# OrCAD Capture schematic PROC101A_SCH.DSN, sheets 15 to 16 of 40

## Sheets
15 38. SoC POWER SUPPLY: size C; title: SoC POWER SUPPLY
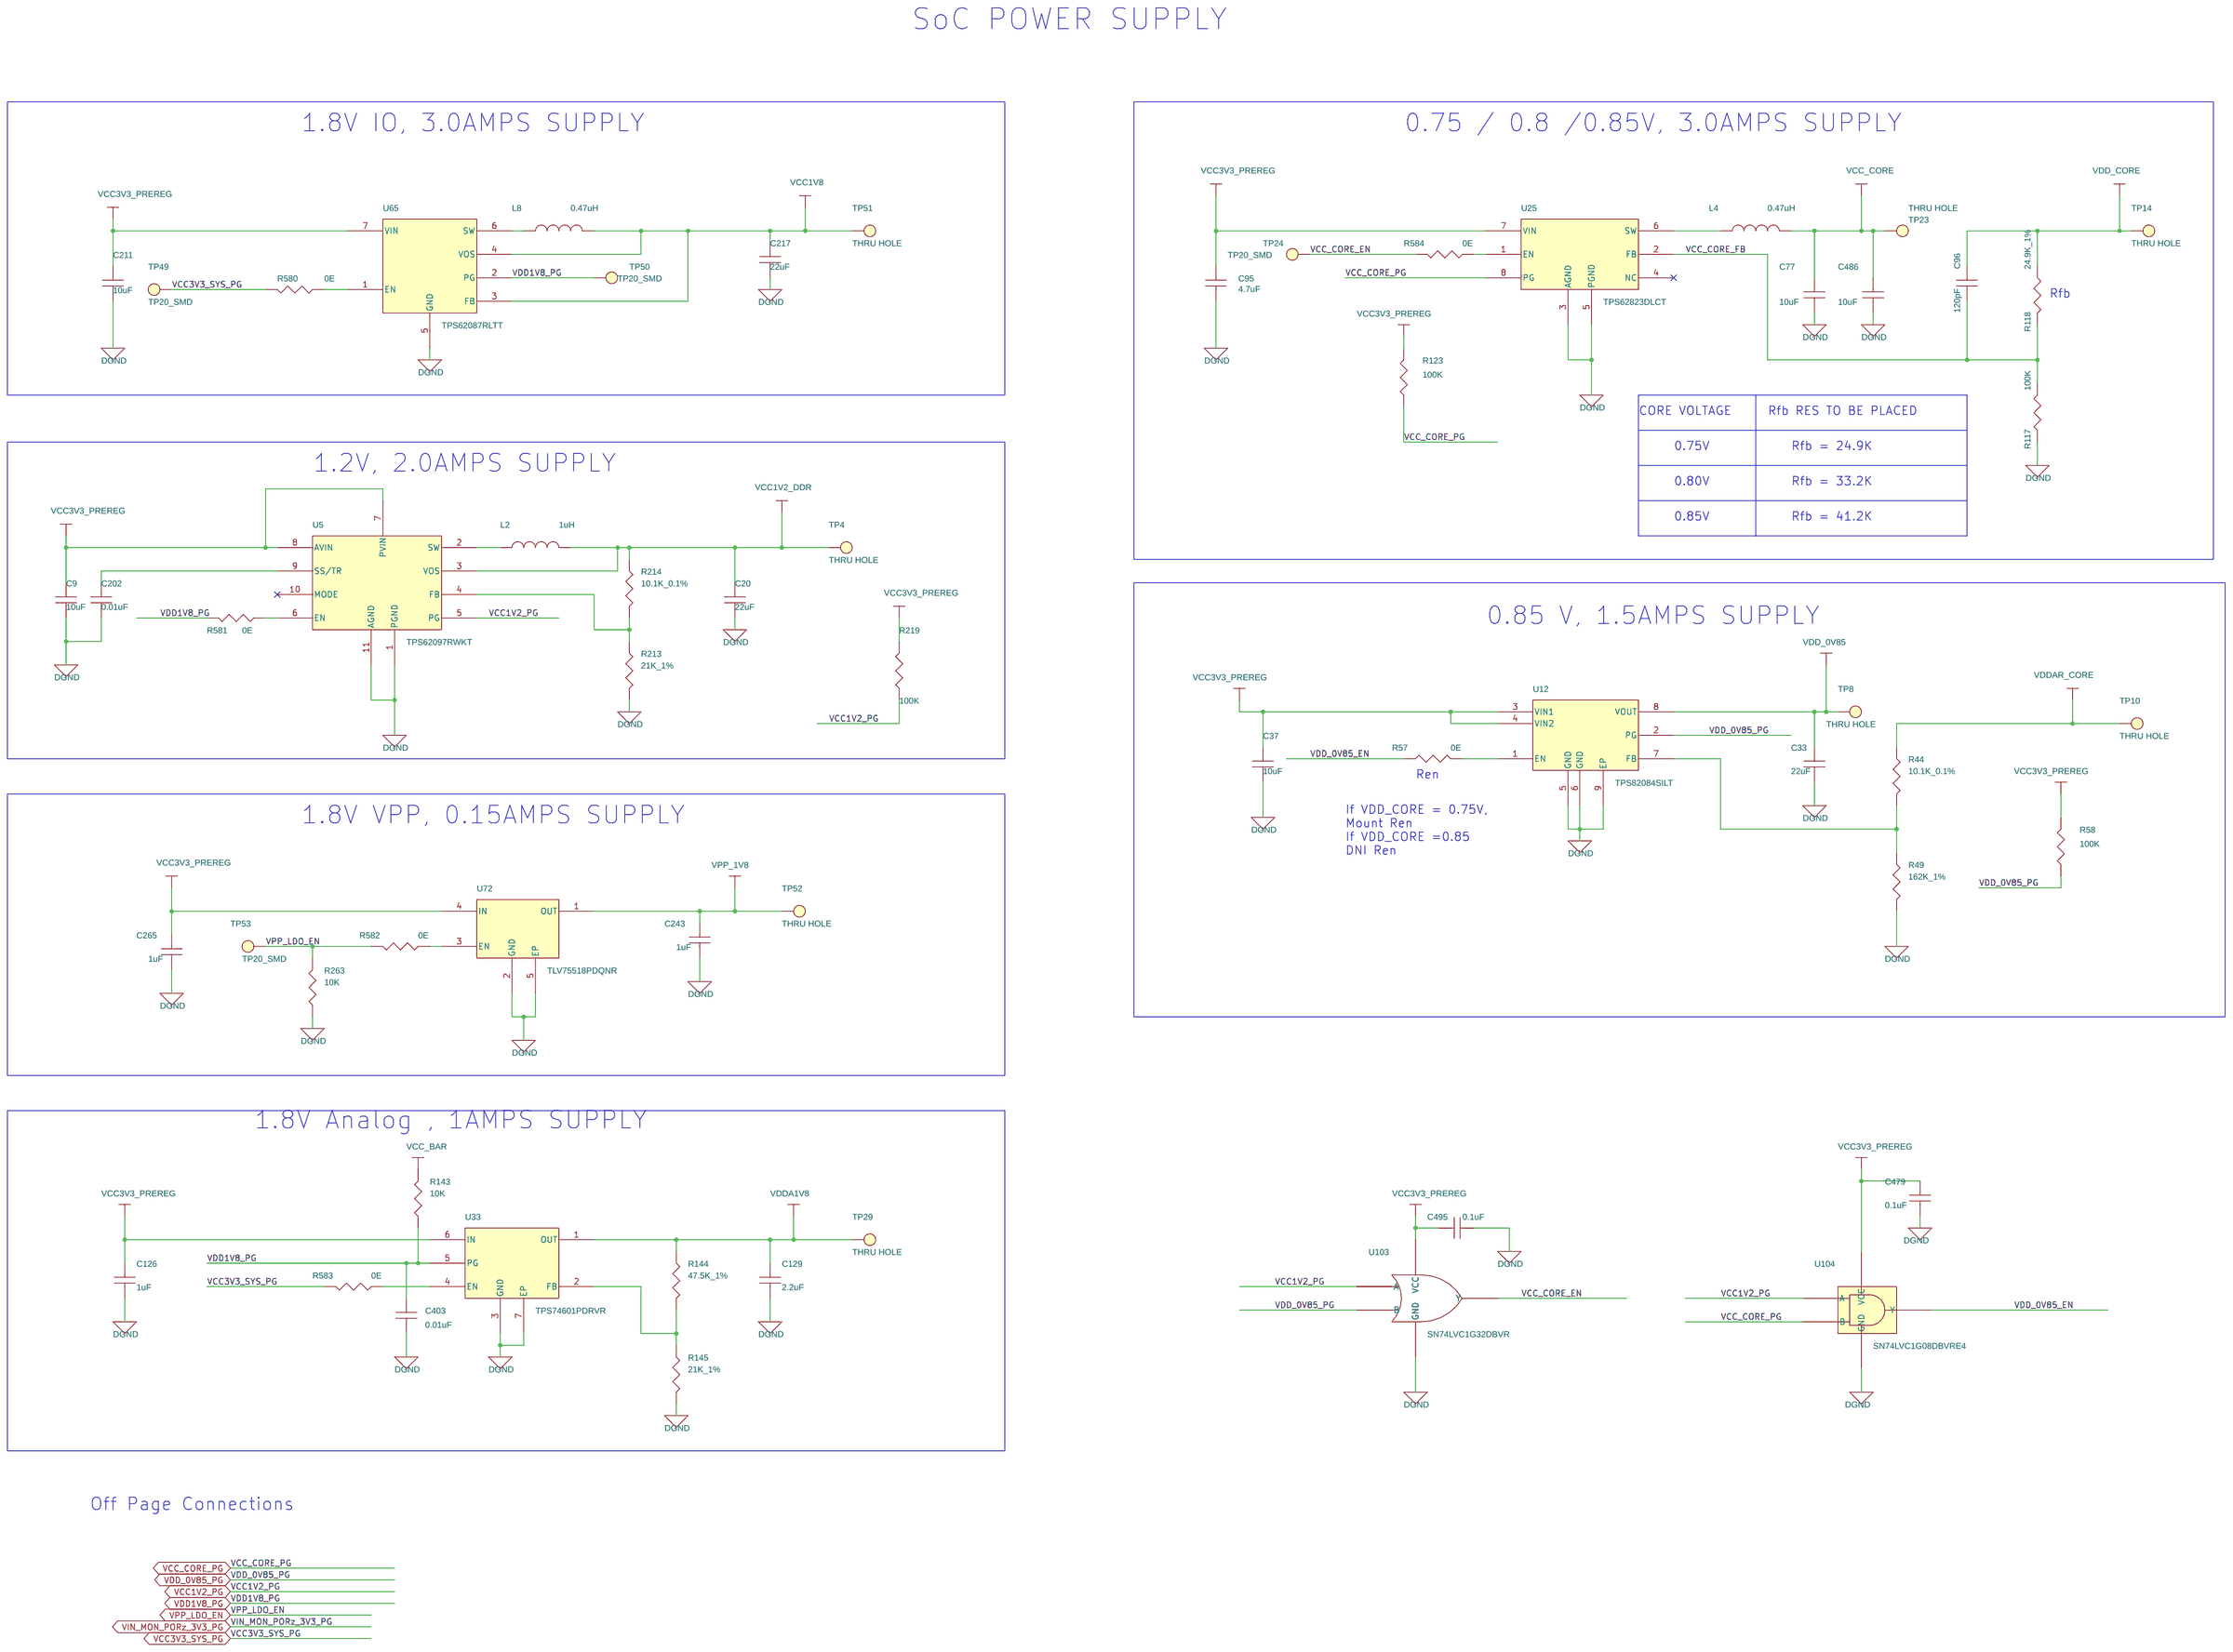
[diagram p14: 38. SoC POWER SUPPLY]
16 39.PERIPHERAL POWER SUPPLY: size C; title: PERIPHERAL POWER SUPPLY
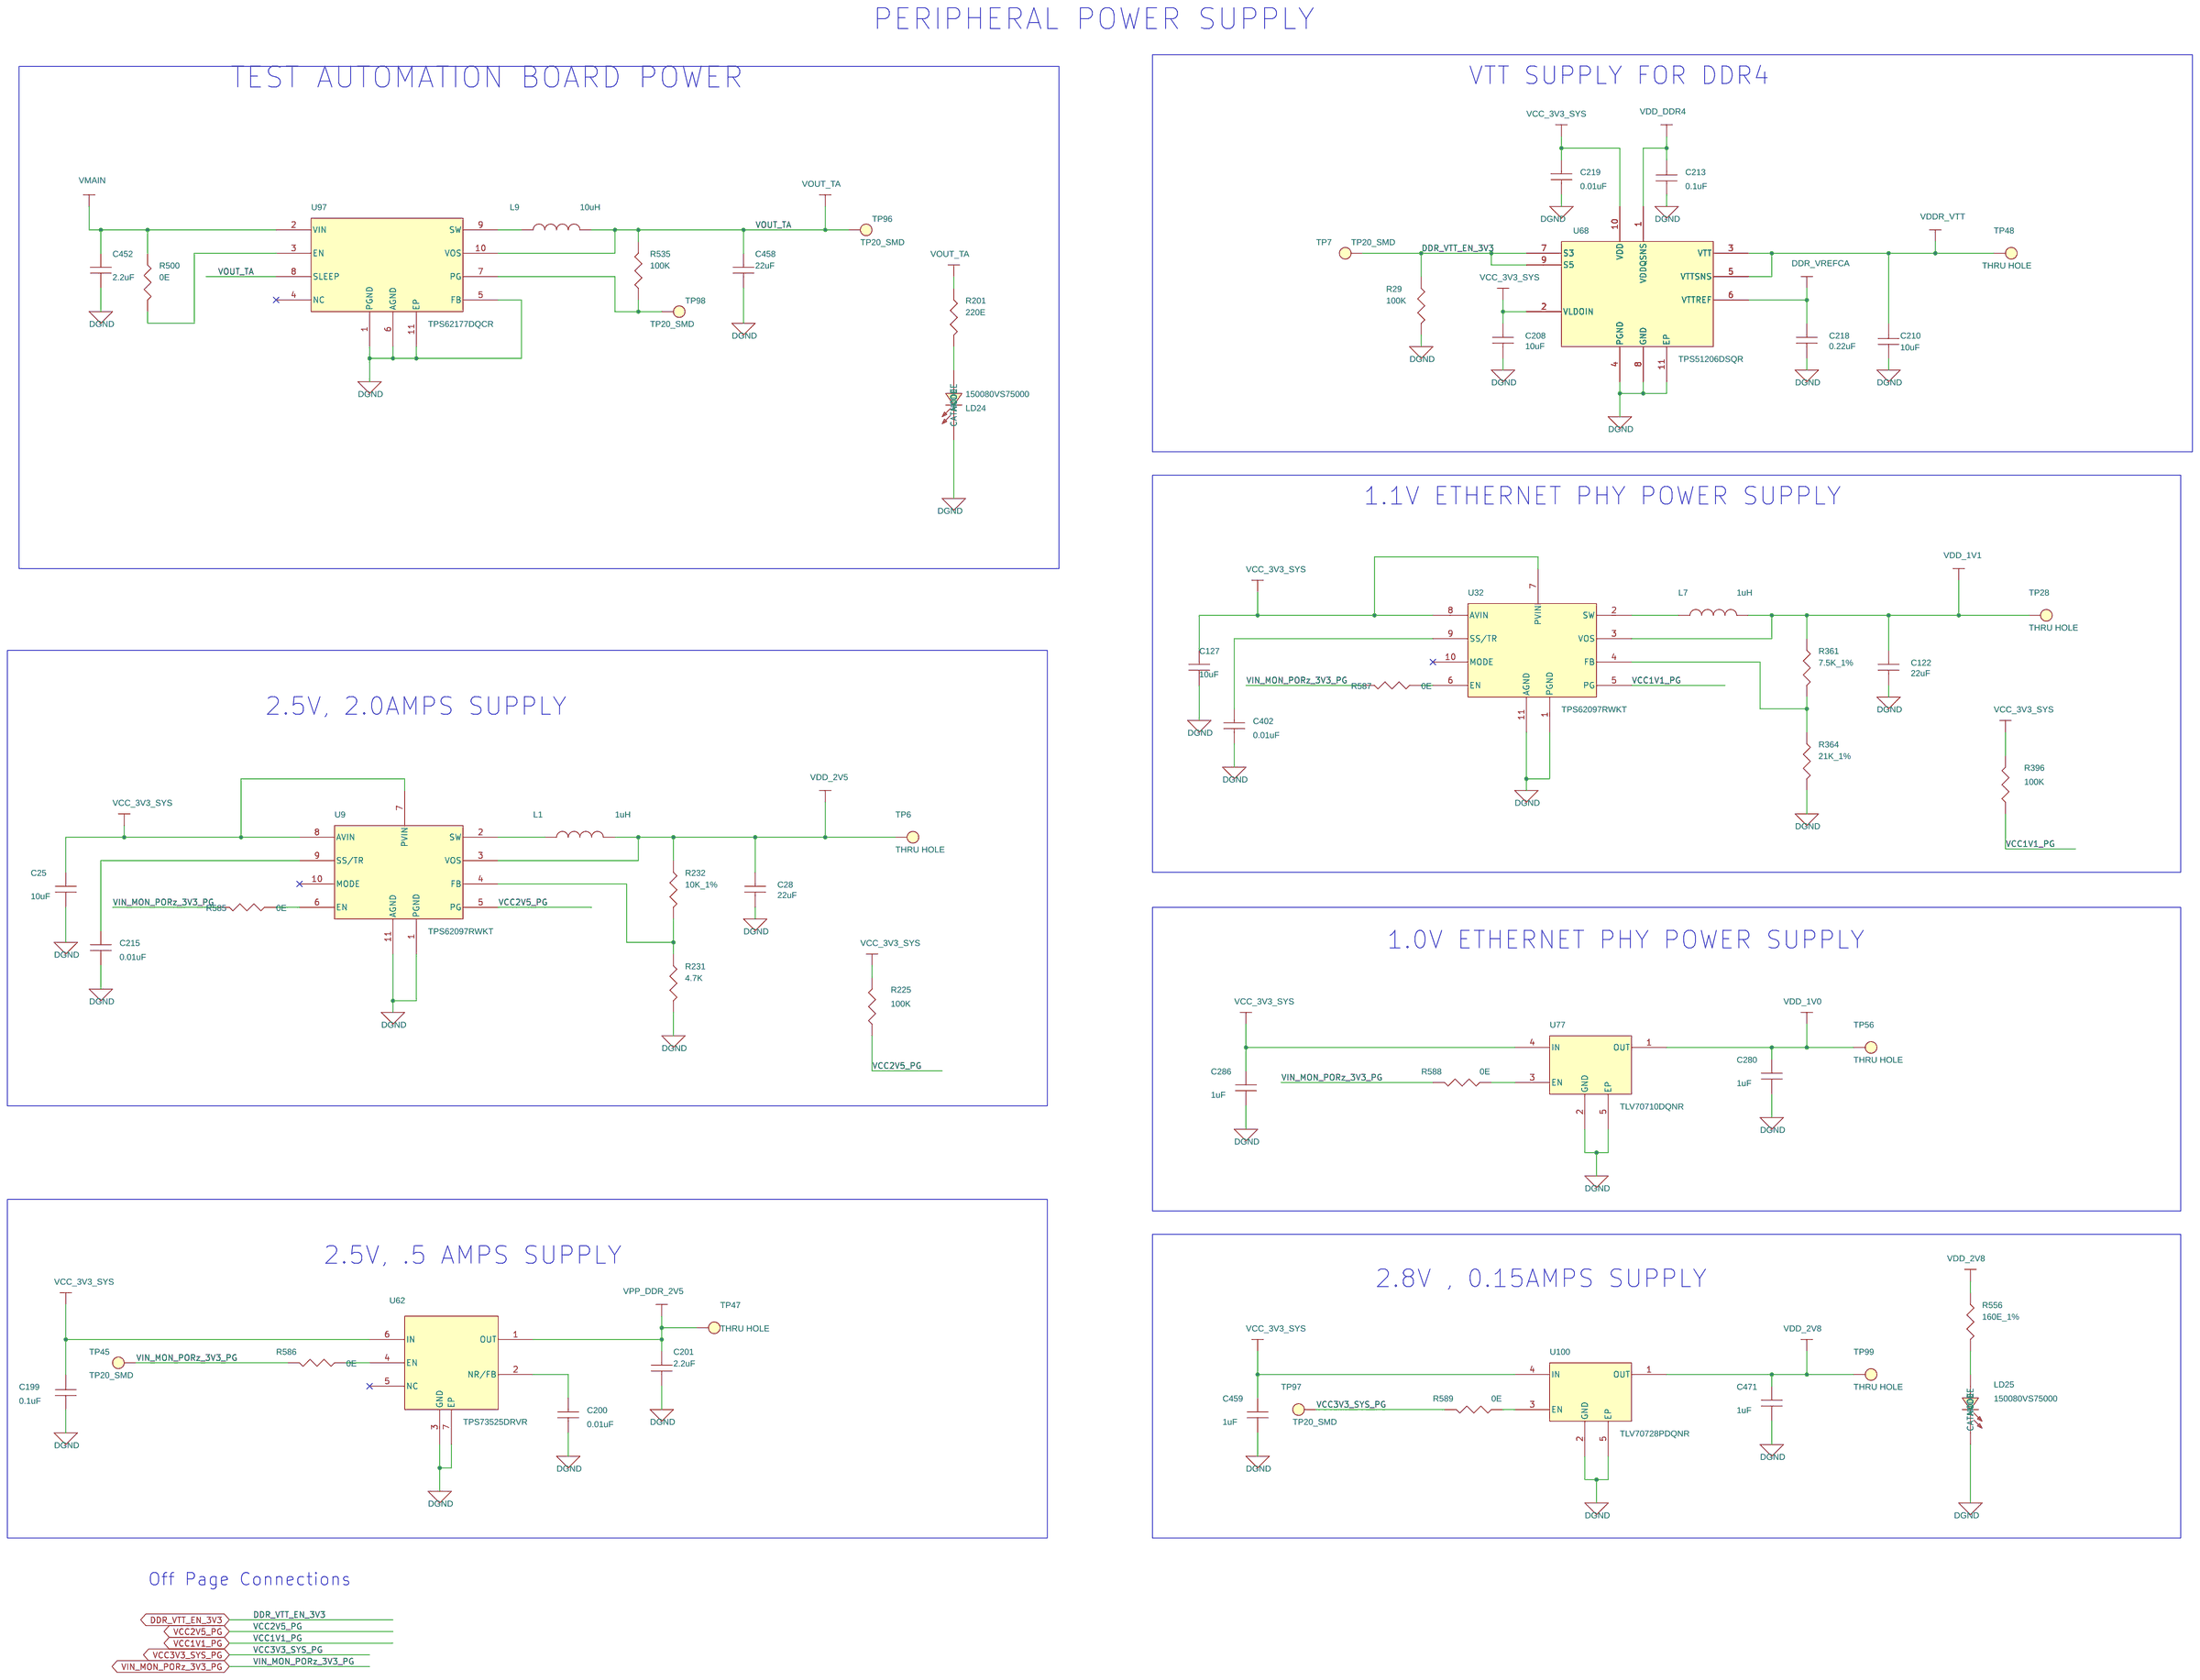
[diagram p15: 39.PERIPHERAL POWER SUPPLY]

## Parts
sheet 38. SoC POWER SUPPLY
C9  10uF  [CAP0402_0-75]
C20  22uF  [CAP0603_1]
C33  22uF  [CAP0603_1]
C37  10uF  [CAP0402_0-75]
C77  10uF  [CAP0402_0-75]
C95  4.7uF  [CAP0603_1]
C96  120pF  [CAP0402_0-75]
C126  1uF  [CAP0402_0-75]
C129  2.2uF  [CAP0402_0-75]
C202  0.01uF  [CAP0402_0-75]
C211  10uF  [CAP0603_1]
C217  22uF  [CAP0603_1]
C243  1uF  [CAP0402_0-75]
C265  1uF  [CAP0402_0-75]
C403  0.01uF  [CAP0402_0-75]
C479  0.1uF  [CAP0402_0-75]
C486  10uF  [CAP0402_0-75]
C495  0.1uF  [CAP0402_0-75]
L2  1uH  [IND_744316100_230X220_SMD_4-3]
L4  0.47uH  [IND_744373460047_270X270_SMD_3]
L8  0.47uH  [IND_744373460047_270X270_SMD_3]
R44  10.1K_0.1%  [RES0603_0-75]
R49  162K_1%  [RES0402_0-5]
R57  0E  [RES0402_0-5]
R58  100K  [RES0402_0-5]
R117  100K  [RES0402_0-5]
R118  24.9K_1%  [RES0402_0-5]
R123  100K  [RES0402_0-5]
R143  10K  [RES0402_0-5]
R144  47.5K_1%  [RES0402_0-5]
R145  21K_1%  [RES0402_0-5]
R213  21K_1%  [RES0402_0-5]
R214  10.1K_0.1%  [RES0603_0-75]
R219  100K  [RES0402_0-5]
R263  10K  [RES0402_0-5]
R580  0E  [RES0402_0-5]
R581  0E  [RES0402_0-5]
R582  0E  [RES0402_0-5]
R583  0E  [RES0402_0-5]
R584  0E  [RES0402_0-5]
TP4  THRU HOLE  [TP_40X65]
TP8  THRU HOLE  [TP_40X65]
TP10  THRU HOLE  [TP_40X65]
TP14  THRU HOLE  [TP_40X65]
TP23  THRU HOLE  [TP_40X65]
TP24  TP20_SMD  [TP20_SMD]
TP29  THRU HOLE  [TP_40X65]
TP49  TP20_SMD  [TP20_SMD]
TP50  TP20_SMD  [TP20_SMD]
TP51  THRU HOLE  [TP_40X65]
TP52  THRU HOLE  [TP_40X65]
TP53  TP20_SMD  [TP20_SMD]
U5  TPS62097RWKT  [VQFNHR11_TPS62097_80X80_1]
U12  TPS82084SILT  [uSIP8_TPS82084_110X120_1-4]
U25  TPS62823DLCT  [VSONHR8_TPS62823_60X80_1]
U33  TPS74601PDRVR  [SON6_25-59_85X85_0-8]
U65  TPS62087RLTT  [VSONHR7_TPS62085_80X80_1]
U72  TLV75518PDQNR  [X2SON4_TLV71318P_40X40_0-4]
U103  SN74LVC1G32DBVR  [SOT23-5_1-5]
U104  SN74LVC1G08DBVRE4  [SOT23-5]
sheet 39.PERIPHERAL POWER SUPPLY
C25  10uF  [CAP0402_0-75]
C28  22uF  [CAP0603_1]
C122  22uF  [CAP0603_1]
C127  10uF  [CAP0402_0-75]
C199  0.1uF  [CAP0402_0-75]
C200  0.01uF  [CAP0402_0-75]
C201  2.2uF  [CAP0402_0-75]
C208  10uF  [CAP0402_0-75]
C210  10uF  [CAP0402_0-75]
C213  0.1uF  [CAP0402_0-75]
C215  0.01uF  [CAP0402_0-75]
C218  0.22uF  [CAP0201_0-5]
C219  0.01uF  [CAP0402_0-75]
C280  1uF  [CAP0402_0-75]
C286  1uF  [CAP0402_0-75]
C402  0.01uF  [CAP0402_0-75]
C452  2.2uF  [CAP0603_1]
C458  22uF  [CAP0805_1-5]
C459  1uF  [CAP0402_0-75]
C471  1uF  [CAP0402_0-75]
L1  1uH  [IND_744316100_230X220_SMD_4-3]
L7  1uH  [IND_744316100_230X220_SMD_4-3]
L9  10uH  [IND_74438336100_130X130_SMD_2]
LD24  150080VS75000  [LED_150080VS75000_80X50_SMD_0-8]
LD25  150080VS75000  [LED_150080VS75000_80X50_SMD_0-8]
R29  100K  [RES0402_0-5]
R201  220E  [RES0402_0-5]
R225  100K  [RES0402_0-5]
R231  4.7K  [RES0402_0-5]
R232  10K_1%  [RES0402_0-5]
R361  7.5K_1%  [RES0402_0-5]
R364  21K_1%  [RES0402_0-5]
R396  100K  [RES0402_0-5]
R500  0E  [RES0402_0-5]
R535  100K  [RES0402_0-5]
R556  160E_1%  [RES0402_0-5]
R585  0E  [RES0402_0-5]
R586  0E  [RES0402_0-5]
R587  0E  [RES0402_0-5]
R588  0E  [RES0402_0-5]
R589  0E  [RES0402_0-5]
TP6  THRU HOLE  [TP_40X65]
TP7  TP20_SMD  [TP20_SMD]
TP28  THRU HOLE  [TP_40X65]
TP45  TP20_SMD  [TP20_SMD]
TP47  THRU HOLE  [TP_40X65]
TP48  THRU HOLE  [TP_40X65]
TP56  THRU HOLE  [TP_40X65]
TP96  TP20_SMD  [TP20_SMD]
TP97  TP20_SMD  [TP20_SMD]
TP98  TP20_SMD  [TP20_SMD]
TP99  THRU HOLE  [TP_40X65]
U9  TPS62097RWKT  [VQFNHR11_TPS62097_80X80_1]
U32  TPS62097RWKT  [VQFNHR11_TPS62097_80X80_1]
U62  TPS73525DRVR  [SON6_25-59_85X85_0-8]
U68  TPS51206DSQR  [EDFN10_15-74_80X80_0-8]
U77  TLV70710DQNR  [X2SON4_TLV71318P_40X40_0-4]
U97  TPS62177DQCR  [WSON10_19-68_80X120_0-8]
U100  TLV70728PDQNR  [X2SON4_TLV71318P_40X40_0-4]

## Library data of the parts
C9 C25 C37 C77 C127 C208 C210 C486 = CAP: CAP CERAMIC 10uF 10V 20% X5R 0402; Chkd/date: MANIRAJA/300520; Crtd /date: ALVY/260520; Custom_Duty: 15%; Customs_HS_Code: 85322990; Distributor_name: DIGIKEY; Distributor_part_number: 490-GRM155R61A106ME11DTR-ND; Footprint Path: Y:\MIS_DATABASE\Library\ALTIUM_TOOL\PCB_FOOTPRINTS\Altium_Footprint_Lib.PcbLib; Height: 0.55MM; Library Path: Y:\MIS_DATABASE\Library\ALTIUM_TOOL\SCHEMATICS_PARTS\MS_DISCRETE_Library.schlib; Mfr_name: MURATA; Mfr_part_number: GRM155R61A106ME11D; Mistral Part No: 120013110019-R; Package: 0402; Part_type: CAPACITORS\CERAMIC; Project: QCS610_NANOSOM; RoHS: RoHS; Temperature: -55°C+85°C; Tolerance: 20%; Voltage: 10V; Wattage: NA; Weight: 3.1mg; Datasheet: Y:\MIS_DATABASE\DATASHEETS\CAPACITORS\MURATA-GXX-SER_NOV17.PDF
C20 C28 C33 C122 C217 = CAP: CAP CERAMIC 22uF 6.3V 20% X5R 0603; Chkd/date: JEBRAN/090915; Crtd /date: JEBRAN/090915; Custom_Duty: 15%; Customs_HS_Code: 85322990; Distributor_name: DIGIKEY; Distributor_part_number: 490-7611-2-ND; Footprint Path: Y:\MIS_DATABASE\Library\ALTIUM_TOOL\PCB_FOOTPRINTS\Altium_Footprint_Lib.PcbLib; Height: 1.00MM; Library Path: Y:\MIS_DATABASE\Library\ALTIUM_TOOL\SCHEMATICS_PARTS\MS_DISCRETE_Library.schlib; Mfr_name: MURATA; Mfr_part_number: GRM188R60J226MEA0; Mistral Part No: 120015090007-R; Package: 0603; Part_type: CAPACITORS\CERAMIC; Project: OCTBTS_3000; RoHS: RoHS; Temperature: -55°C+85°C; Tolerance: 20%; Voltage: 6.3V; Wattage: NA; Weight: 6.3mg; Datasheet: Y:\MIS_DATABASE\DATASHEETS\CAPACITORS\MURATA-GXX-SER_NOV17.PDF
C95 = CAP: CAP CERAMIC 4.7uF 16V 10% X5R 0603; Chkd/date: MANIRAJA/131217; Crtd /date: ALVY/131217; Custom_Duty: 15%; Customs_HS_Code: 85322990; Distributor_name: DIGIKEY; Distributor_part_number: 311-1785-1-ND; Footprint Path: Y:\MIS_DATABASE\Library\ALTIUM_TOOL\PCB_FOOTPRINTS\Altium_Footprint_Lib.PcbLib; Height: 0.95MM; Library Path: Y:\MIS_DATABASE\Library\ALTIUM_TOOL\SCHEMATICS_PARTS\MS_DISCRETE_Library.schlib; Mfr_name: YAGEO AMERICA; Mfr_part_number: CC0603KRX5R7BB475; Mistral Part No: 120011050004-R; Package: 0603; Part_type: CAPACITORS\CERAMIC; Project: ASL_LIU_TYPE-II; RoHS: RoHS; Temperature: -55°C+85°C; Tolerance: 10%; Voltage: 16V; Wattage: NA; Weight: 2mg; Datasheet: Y:\MIS_DATABASE\DATASHEETS\CAPACITORS\YACC-X5R.PDF
C96 = CAP: CAP CERAMIC 120pF 50V 5% C0G(NP0) 0402; Chkd/date: MANIRAJA/080520; Crtd /date: ALVY/070520; Custom_Duty: 15%; Customs_HS_Code: 85322990; Distributor_name: DIGIKEY; Distributor_part_number: 311-3337-1-ND; Footprint Path: Y:\MIS_DATABASE\Library\ALTIUM_TOOL\PCB_FOOTPRINTS\Altium_Footprint_Lib.PcbLib; Height: 0.55MM; Library Path: Y:\MIS_DATABASE\Library\ALTIUM_TOOL\SCHEMATICS_PARTS\MS_DISCRETE_Library.schlib; Mfr_name: YAGEO AMERICA; Mfr_part_number: CC0402JRNPO9BN121; Mistral Part No: 120014040005-R; Package: 0402; Part_type: CAPACITORS\CERAMIC; Project: AM64x-GP_EVM BRD; RoHS: RoHS; Temperature: -55°C+125°C; Tolerance: 5%; Voltage: 50V; Wattage: NA; Weight: 12mg; Datasheet: Y:\MIS_DATABASE\DATASHEETS\CAPACITORS\YACC-NPO.PDF
C126 C243 C265 C280 C286 C459 C471 = CAP: CAP CERAMIC 1uF 10V 20% X5R 0402; Chkd/date: MANIRAJA/210820; Crtd /date: ALVY/190820; Custom_Duty: 15%; Customs_HS_Code: 85322990; Distributor_name: DIGIKEY; Distributor_part_number: 732-7489-1-ND; Footprint Path: Y:\MIS_DATABASE\Library\ALTIUM_TOOL\PCB_FOOTPRINTS\Altium_Footprint_Lib.PcbLib; Height: 0.55MM; Library Path: Y:\MIS_DATABASE\Library\ALTIUM_TOOL\SCHEMATICS_PARTS\MS_DISCRETE_Library.schlib; Mfr_name: WURTH ELECTRONICS; Mfr_part_number: 885012105012; Mistral Part No: 120020080009-R; Package: 0402; Part_type: CAPACITORS\CERAMIC; Project: AM64x_EVM_BRD; RoHS: RoHS; Temperature: -55°C+85°C; Tolerance: 20%; Voltage: 10V; Wattage: NA; Weight: 0.65mg; Datasheet: Y:\MIS_DATABASE\DATASHEETS\CAPACITORS\885012105012.PDF
C129 C201 = CAP: CAP CERAMIC 2.2uF 10V 20% X5R 0402; Chkd/date: MANIRAJA/170820; Crtd /date: ALVY/170820; Custom_Duty: 15%; Customs_HS_Code: 85322990; Distributor_name: DIGIKEY; Distributor_part_number: 732-7490-1-ND; Footprint Path: Y:\MIS_DATABASE\Library\ALTIUM_TOOL\PCB_FOOTPRINTS\Altium_Footprint_Lib.PcbLib; Height: 0.55MM; Library Path: Y:\MIS_DATABASE\Library\ALTIUM_TOOL\SCHEMATICS_PARTS\MS_DISCRETE_Library.schlib; Mfr_name: WURTH ELECTRONICS; Mfr_part_number: 885012105013; Mistral Part No: 120019040036-R; Package: 0402; Part_type: CAPACITORS\CERAMIC; Project: AM64x_EVM_BRD; RoHS: RoHS; Temperature: -55°C+85°C; Tolerance: 20%; Voltage: 10V; Wattage: NA; Weight: 0.65mg; Datasheet: Y:\MIS_DATABASE\DATASHEETS\CAPACITORS\885012105013.PDF
C200 C202 C215 C219 C402 C403 = CAP: CAP CERAMIC 0.01uF 25V 10% X7R 0402; Chkd/date: MANIRAJA/170820; Crtd /date: ALVY/170820; Custom_Duty: 15%; Customs_HS_Code: 85322990; Distributor_name: DIGIKEY; Distributor_part_number: 732-7545-1-ND; Footprint Path: Y:\MIS_DATABASE\Library\ALTIUM_TOOL\PCB_FOOTPRINTS\Altium_Footprint_Lib.PcbLib; Height: 0.55MM; Library Path: Y:\MIS_DATABASE\Library\ALTIUM_TOOL\SCHEMATICS_PARTS\MS_DISCRETE_Library.schlib; Mfr_name: WURTH ELECTRONICS; Mfr_part_number: 885012205050; Mistral Part No: 120011090040-R; Package: 0402; Part_type: CAPACITORS\CERAMIC; Project: AM64x_EVM_BRD; RoHS: RoHS; Temperature: -55°C+125°C; Tolerance: 10%; Voltage: 25V; Wattage: NA; Weight: 0.65mg; Datasheet: Y:\MIS_DATABASE\DATASHEETS\CAPACITORS\885012205050.PDF
C211 = CAP: CAP CERAMIC 10uF 35V 20% X5R 0603; Chkd/date: MANIRAJA/170519; Crtd /date: ALVY/160519; Custom_Duty: 15%; Customs_HS_Code: 85322990; Distributor_name: DIGIKEY; Distributor_part_number: 490-13248-1-ND; Footprint Path: Y:\MIS_DATABASE\Library\ALTIUM_TOOL\PCB_FOOTPRINTS\Altium_Footprint_Lib.PcbLib; Height: 1.00MM; Library Path: Y:\MIS_DATABASE\Library\ALTIUM_TOOL\SCHEMATICS_PARTS\MS_DISCRETE_Library.schlib; Mfr_name: MURATA; Mfr_part_number: GRM188R6YA106MA73D; Mistral Part No: 120019050016-R; Package: 0603; Part_type: CAPACITORS\CERAMIC; Project: BRUKER_SD820_COMMONDO; RoHS: RoHS; Temperature: -55°C+85°C; Tolerance: 20%; Voltage: 35V; Wattage: NA; Weight: 9mg; Datasheet: Y:\MIS_DATABASE\DATASHEETS\CAPACITORS\GRM188R6YA106MA73.PDF
C199 C213 C479 C495 = CAP: CAP CERAMIC 0.1uF 25V 20% X5R 0402; Alt_Mfr_name: YAGEO AMERICA; Alt_Mfr_part_number: CC0402KRX5R8BB104; Chkd/date: MANIRAJA/170820; Crtd /date: ALVY/170820; Custom_Duty: 15%; Customs_HS_Code: 85322990; Distributor_name: DIGIKEY; Distributor_part_number: 732-7495-1-ND; Footprint Path: Y:\MIS_DATABASE\Library\ALTIUM_TOOL\PCB_FOOTPRINTS\Altium_Footprint_Lib.PcbLib; Height: 0.55MM; Library Path: Y:\MIS_DATABASE\Library\ALTIUM_TOOL\SCHEMATICS_PARTS\MS_DISCRETE_Library.schlib; Mfr_name: WURTH ELECTRONICS; Mfr_part_number: 885012105018; Mistral Part No: 120020080003-R; Package: 0402; Part_type: CAPACITORS\CERAMIC; Project: AM64x_EVM_BRD; RoHS: RoHS; Temperature: -55°C+85°C; Tolerance: 20%; Voltage: 25V; Wattage: NA; Weight: 0.65mg; Datasheet: Y:\MIS_DATABASE\DATASHEETS\CAPACITORS\885012105018.PDF
L1 L2 L7 = INDUCTOR: IND HI-CURRENT 1uH 11.5A 20% SMD; Chkd/date: MANIRAJA/280520; Crtd /date: ALVY/280520; Custom_Duty: 24%; Customs_HS_Code: 85437099; Distributor_name: DIGIKEY; Distributor_part_number: 732-6176-1-ND; Footprint Path: Y:\MIS_DATABASE\Library\ALTIUM_TOOL\PCB_FOOTPRINTS\Altium_Footprint_Lib.PcbLib; Height: 4.30MM; Library Path: Y:\MIS_DATABASE\Library\ALTIUM_TOOL\SCHEMATICS_PARTS\MS_DISCRETE_Library.schlib; Mfr_name: WURTH ELECTRONICS; Mfr_part_number: 744316100; Mistral Part No: 130020050041-R; Package: SMD; Project: AM64x-GP_EVM BRD; RoHS: RoHS; Temperature: -40°C+150°C; Tolerance: 20%; Voltage: NA; Wattage: NA; Weight: 570mg; Datasheet: Y:\MIS_DATABASE\DATASHEETS\DISCRETES\INDUCTORS\744316100.PDF
L4 L8 = INDUCTOR: IND POWER 0.47uH 11.5A 20% SMD; Chkd/date: MANIRAJA/130820; Crtd /date: ALVY/130820; Custom_Duty: 24%; Customs_HS_Code: 85437099; Distributor_name: DIGIKEY; Distributor_part_number: 732-3366-1-ND; Footprint Path: Y:\MIS_DATABASE\Library\ALTIUM_TOOL\PCB_FOOTPRINTS\Altium_Footprint_Lib.PcbLib; Height: 3.00MM; Library Path: Y:\MIS_DATABASE\Library\ALTIUM_TOOL\SCHEMATICS_PARTS\MS_DISCRETE_Library.schlib; Mfr_name: WURTH ELECTRONICS; Mfr_part_number: 744373460047; Mistral Part No: 130020080011-R; Package: SMD; Project: AM64x_EVM_BRD; RoHS: RoHS; Temperature: -40°C+125°C; Tolerance: 20%; Voltage: NA; Wattage: NA; Weight: 719mg; Datasheet: Y:\MIS_DATABASE\DATASHEETS\DISCRETES\INDUCTORS\744373460047.PDF
R44 R214 = RESISTOR: RES 10.1K 1/8W 0.1% AUTO 0603; Chkd/date: MANIRAJA/090420; Crtd /date: ALVY/080420; Custom_Duty: 15%; Customs_HS_Code: 85332119; Distributor_name: DIGIKEY; Distributor_part_number: 541-3907-1-ND; Footprint Path: Y:\MIS_DATABASE\Library\ALTIUM_TOOL\PCB_FOOTPRINTS\Altium_Footprint_Lib.PcbLib; Height: 0.55MM; Library Path: Y:\MIS_DATABASE\Library\ALTIUM_TOOL\SCHEMATICS_PARTS\MS_DISCRETE_Library.schlib; Mfr_name: VISHAY; Mfr_part_number: TNPW060310K1BEEA; Mistral Part No: 110020040008-R; Package: 0603; Part_type: RESISTORS\FIXED; Project: AM64x-GP_EVM BRD; RoHS: RoHS; Temperature: -55°C+155°C; Tolerance: 0.1%; Voltage: NA; Wattage: 1/8W; Weight: 25mg; Datasheet: Y:\MIS_DATABASE\DATASHEETS\RESISTORS\VISHAY_TNPWE3.PDF
R49 = RESISTOR: RES 162K 1/10W 1% 0402; Chkd/date: SUHAS/270910; Crtd /date: MUDDU/190610; Custom_Duty: 15%; Customs_HS_Code: 85332119; Distributor_name: DIGIKEY; Distributor_part_number: P162KLCT-ND; Footprint Path: Y:\MIS_DATABASE\Library\ALTIUM_TOOL\PCB_FOOTPRINTS\Altium_Footprint_Lib.PcbLib; Height: 0.40MM; Library Path: Y:\MIS_DATABASE\Library\ALTIUM_TOOL\SCHEMATICS_PARTS\MS_DISCRETE_Library.schlib; Mfr_name: PANASONIC-ECG; Mfr_part_number: ERJ-2RKF1623X; Mistral Part No: 110010060019-R; Package: 0402; Part_type: RESISTORS\FIXED; Project: CENTAURUS; RoHS: RoHS; Temperature: -55°C+155°C; Tolerance: 1%; Voltage: NA; Wattage: 1/10W; Weight: 0.8mg; Datasheet: Y:\MIS_DATABASE\DATASHEETS\RESISTORS\PAN-ERJSER_NOV17.PDF
R57 R500 R580-R589 = RESISTOR: RES 0E 1/16W JUMPER 0402; Chkd/date: VASANTHA/201216; Crtd /date: MUDDU/190810; Custom_Duty: 15%; Customs_HS_Code: 85332119; Distributor_name: DIGIKEY; Distributor_part_number: 541-0.0JCT-ND; Footprint Path: Y:\MIS_DATABASE\Library\ALTIUM_TOOL\PCB_FOOTPRINTS\Altium_Footprint_Lib.PcbLib; Height: 0.40MM; Library Path: Y:\MIS_DATABASE\Library\ALTIUM_TOOL\SCHEMATICS_PARTS\MS_DISCRETE_Library.schlib; Mfr_name: VISHAY; Mfr_part_number: CRCW04020000Z0ED; Mistral Part No: 110010080019-R; Package: 0402; Part_type: RESISTORS\FIXED; Project: PB_BUGBASE; RoHS: RoHS; Temperature: -55°C+155°C; Tolerance: NA; Voltage: NA; Wattage: 1/16W; Weight: 0.65mg; Datasheet: Y:\MIS_DATABASE\DATASHEETS\RESISTORS\CRCW0603.PDF
R29 R58 R117 R123 R219 R225 R396 R535 = RESISTOR: RES 100K 1/16W 5% 0402; Chkd/date: VASANTHA/061216; Crtd /date: BAVISH/010611; Custom_Duty: 15%; Customs_HS_Code: 85332119; Distributor_name: DIGIKEY; Distributor_part_number: 541-100KJCT-ND; Footprint Path: Y:\MIS_DATABASE\Library\ALTIUM_TOOL\PCB_FOOTPRINTS\Altium_Footprint_Lib.PcbLib; Height: 0.40MM; Library Path: Y:\MIS_DATABASE\Library\ALTIUM_TOOL\SCHEMATICS_PARTS\MS_DISCRETE_Library.schlib; Mfr_name: VISHAY; Mfr_part_number: CRCW0402100KJNED; Mistral Part No: 110011060002-R; Package: 0402; Part_type: RESISTORS\FIXED; Project: AM4515_EVM_LCD; RoHS: RoHS; Temperature: -55°C+155°C; Tolerance: 5%; Voltage: NA; Wattage: 1/16W; Weight: 0.65mg; Datasheet: Y:\MIS_DATABASE\DATASHEETS\RESISTORS\CRCW0603.PDF
R118 = RESISTOR: RES 24.9K 1/16W 1% 0402; Chkd/date: MANIRAJA/080520; Crtd /date: ALVY/070520; Custom_Duty: 15%; Customs_HS_Code: 85332119; Distributor_name: DIGIKEY; Distributor_part_number: 541-24.9KLCT-ND; Footprint Path: Y:\MIS_DATABASE\Library\ALTIUM_TOOL\PCB_FOOTPRINTS\Altium_Footprint_Lib.PcbLib; Height: 0.40MM; Library Path: Y:\MIS_DATABASE\Library\ALTIUM_TOOL\SCHEMATICS_PARTS\MS_DISCRETE_Library.schlib; Mfr_name: VISHAY; Mfr_part_number: CRCW040224K9FKED; Mistral Part No: 110009030538-R; Package: 0402; Part_type: RESISTORS\FIXED; Project: AM64x-GP_EVM BRD; RoHS: RoHS; Temperature: -55°C+155°C; Tolerance: 1%; Voltage: NA; Wattage: 1/16W; Weight: 0.65mg; Datasheet: Y:\MIS_DATABASE\DATASHEETS\RESISTORS\CRCW0603.PDF
R143 R263 = RESISTOR: RES 10K 1/16W 5% 0402; Chkd/date: VASANTHA/061216; Crtd /date: MAZHAR/230805; Custom_Duty: 15%; Customs_HS_Code: 85332119; Distributor_name: DIGIKEY; Distributor_part_number: 311-10KJRCT-ND; Footprint Path: Y:\MIS_DATABASE\Library\ALTIUM_TOOL\PCB_FOOTPRINTS\Altium_Footprint_Lib.PcbLib; Height: 0.40MM; Library Path: Y:\MIS_DATABASE\Library\ALTIUM_TOOL\SCHEMATICS_PARTS\MS_DISCRETE_Library.schlib; Mfr_name: YAGEO AMERICA; Mfr_part_number: RC0402JR-0710KL; Mistral Part No: 110011060021-R; Package: 0402; Part_type: RESISTORS\FIXED; Project: HSE; RoHS: RoHS; Temperature: -55°C+155°C; Tolerance: 5%; Voltage: NA; Wattage: 1/16W; Weight: 0.65mg; Datasheet: Y:\MIS_DATABASE\DATASHEETS\RESISTORS\RCXXXXL-SER_MAR18.PDF
R144 = RESISTOR: RES 47.5K 1/16W 1% 0402; Chkd/date: MANIRAJA/170320; Crtd /date: MANIRAJA/170320; Custom_Duty: 15%; Customs_HS_Code: 85332119; Distributor_name: DIGIKEY; Distributor_part_number: 541-47.5KLCT-ND; Footprint Path: Y:\MIS_DATABASE\Library\ALTIUM_TOOL\PCB_FOOTPRINTS\Altium_Footprint_Lib.PcbLib; Height: 0.40MM; Library Path: Y:\MIS_DATABASE\Library\ALTIUM_TOOL\SCHEMATICS_PARTS\MS_DISCRETE_Library.schlib; Mfr_name: VISHAY; Mfr_part_number: CRCW040247K5FKED; Mistral Part No: 110017010006-R; Package: 0402; Part_type: RESISTORS\FIXED; Project: TPR12_SVB; RoHS: RoHS; Temperature: -55°C+155°C; Tolerance: 1%; Voltage: NA; Wattage: 1/16W; Weight: 0.65mg; Datasheet: Y:\MIS_DATABASE\DATASHEETS\RESISTORS\CRCW0603.PDF
R145 R213 R364 = RESISTOR: RES 21K 1/16W 1% 0402; Chkd/date: MANIRAJA/200319; Crtd /date: MANIRAJA/200319; Custom_Duty: 15%; Customs_HS_Code: 85332119; Distributor_name: DIGIKEY; Distributor_part_number: 311-21.0KLRCT-ND; Footprint Path: Y:\MIS_DATABASE\Library\ALTIUM_TOOL\PCB_FOOTPRINTS\Altium_Footprint_Lib.PcbLib; Height: 0.40MM; Library Path: Y:\MIS_DATABASE\Library\ALTIUM_TOOL\SCHEMATICS_PARTS\MS_DISCRETE_Library.schlib; Mfr_name: YAGEO AMERICA; Mfr_part_number: RC0402FR-0721KL; Mistral Part No: 110015080019-R; Package: 0402; Part_type: RESISTORS\FIXED; Project: OCTASIC_3000; RoHS: RoHS; Temperature: -55°C+155°C; Tolerance: 1%; Voltage: NA; Wattage: 1/16W; Weight: 0.65mg; Datasheet: Y:\MIS_DATABASE\DATASHEETS\RESISTORS\RCXXXXL-SER_MAR18.PDF
TP4 TP6 TP8 TP10 TP14 TP23 TP28 TP29 TP47 TP48 TP51 TP52 TP56 TP99 = TESTPOINT: TESTPOINT 1.0MM DRILL PTH; Chkd/date: MAZHAR/271211; Crtd /date: SHREESHAIL/041005; Distributor_name: NA; Distributor_part_number: NA; Height: NA; Mfr_name: LOCAL; Mistral Part No: 130009030938; Package: THRU-HOLE; Project: HSE; Datasheet: NA
TP7 TP24 TP45 TP49 TP50 TP53 TP96-TP98 = TESTPOINT: TESTPOINT CIR 20 SMD; Chkd/date: SHREESHAIL/171006; Crtd /date: MAZHAR/171006; Custom_Duty: NA; Customs_HS_Code: NA; Distributor_name: NA; Distributor_part_number: NA; Footprint Path: Y:\MIS_DATABASE\Library\ALTIUM_TOOL\PCB_FOOTPRINTS\Altium_Footprint_Lib.PcbLib; Height: NA; Library Path: Y:\MIS_DATABASE\Library\ALTIUM_TOOL\SCHEMATICS_PARTS\MS_DISCRETE_Library.schlib; MECHANICAL 3D STEP FILE: NA; Mfr_name: LOCAL; Mistral Part No: NA; Package: SMD; Project: BT MODULE_CSRBC04; RoHS: NA; Temperature: NA; Tolerance: NA; Voltage: NA; Wattage: NA; Weight: NA; Datasheet: NA
U5 U9 U32 = TPS62097RWKT_VQFNHR11: IC 2A SYNCHRONOUS STEP DOWN CONVERTER WITH IDCS CONTROL VQFN-HR11; Chkd/date: MANIRAJA/270917; Crtd /date: MANIRAJA/270917; Custom_Duty: 15%; Customs_HS_Code: 85423100; Distributor_name: DIGIKEY; Distributor_part_number: 296-43330-1-ND; Height: 1.00MM; Mfr_name: TEXAS INSTRUMENTS; Mistral Part No: 142017090025-R; Package: VQFN-HR11; Part_type: ICS\POWER\CONVERTER; Project: TI_MAXIE_CPB; RoHS: RoHS; Temperature: -40°C+125°C; Tolerance: NA; Voltage: NA; Wattage: NA; Weight: NA; Datasheet: Y:\MIS_DATABASE\DATASHEETS\ICS\POWER\TPS62097.PDF
U12 = TPS82084_USIP8: IC 2A STEP DOWN CONVERTER MICROSIP POWER MODULE WITH INTEGRATED INDUCTOR uSIP8; Chkd/date: MANIRAJA/090420; Crtd /date: ALVY/080420; Custom_Duty: 15%; Customs_HS_Code: 85423100; Distributor_name: DIGIKEY; Distributor_part_number: 296-42973-1-ND; Footprint Path: Y:\MIS_DATABASE\Library\ALTIUM_TOOL\PCB_FOOTPRINTS\Altium_Footprint_Lib.PcbLib; Height: 1.33MM; Library Path: Y:\MIS_DATABASE\Library\ALTIUM_TOOL\SCHEMATICS_PARTS\MS_MISCPOWER_Library.schlib; Library Ref: TPS82084_uSIP8; Mfr_name: TEXAS INSTRUMENTS; Mistral Part No: 142020040012-R; Package: uSIP8; Part_type: ICS\POWER\POWER MODULE; Project: AM64x-GP_EVM BRD; RoHS: RoHS; Temperature: -40°C+125°C; Tolerance: NA; Voltage: NA; Wattage: NA; Weight: 580mg; Datasheet: Y:\MIS_DATABASE\DATASHEETS\ICS\POWER\TPS8208X.PDF
U25 = TPS62823_VSONHR8: IC 3A ADJ STEP-DOWN CONVERTER WITH 1% ACCURACY VSON-HR8; Chkd/date: MANIRAJA/080520; Crtd /date: ALVY/070520; Custom_Duty: 15%; Customs_HS_Code: 85423100; Distributor_name: DIGIKEY; Distributor_part_number: 296-50225-1-ND; Footprint Path: Y:\MIS_DATABASE\Library\ALTIUM_TOOL\PCB_FOOTPRINTS\Altium_Footprint_Lib.PcbLib; Height: 1.00MM; Library Path: Y:\MIS_DATABASE\Library\ALTIUM_TOOL\SCHEMATICS_PARTS\MS_MISCPOWER_Library.schlib; Mfr_name: TEXAS INSTRUMENTS; Mistral Part No: 142020050005-R; Package: VSON-HR8; Part_type: ICS\POWER\DC-DC CONVERTER; Project: AM64x-GP_EVM BRD; RoHS: RoHS; Temperature: -40°C+125°C; Tolerance: NA; Voltage: NA; Wattage: NA; Weight: 6.2mg; Datasheet: Y:\MIS_DATABASE\DATASHEETS\ICS\POWER\TPS62821-2-3.PDF
U33 = TPS74501_WSON6: IC 1A ADJ OUTPUT LDO WITH POWER-GOOD WSON6; Chkd/date: MANIRAJA/060619; Crtd /date: ALVY/060619; Custom_Duty: 15%; Customs_HS_Code: 85423100; Distributor_name: MOUSER; Distributor_part_number: 595-TPS74601PDRVR; Footprint Path: Y:\MIS_DATABASE\Library\ALTIUM_TOOL\PCB_FOOTPRINTS\Altium_Footprint_Lib.PcbLib; Height: 0.80MM; Library Path: Y:\MIS_DATABASE\Library\ALTIUM_TOOL\SCHEMATICS_PARTS\MS_MISCPOWER_Library.schlib; Mfr_name: TEXAS INSTRUMENTS; Mistral Part No: 142019060004-R; Package: WSON6; Part_type: ICS\POWER\VOLTAGE REGULATOR; Project: TI_MAXIE_CPB; RoHS: RoHS; Temperature: -40°C+125°C; Tolerance: NA; Voltage: NA; Wattage: NA; Weight: NA; Datasheet: Y:\MIS_DATABASE\DATASHEETS\ICS\POWER\TPS74601.PDF
U65 = TPS62085RLTR_VSONHR7: IC 3A 1.8V STEP DOWN CONVERTER WITH SHORT CIRCUIT PROTECTION VSON-HR7; Chkd/date: MANIRAJA/310818; Crtd /date: MANIRAJA/310818; Custom_Duty: 15%; Customs_HS_Code: 85423100; Distributor_name: DIGIKEY; Distributor_part_number: 296-37087-1-ND; Footprint Path: Y:\MIS_DATABASE\Library\ALTIUM_TOOL\PCB_FOOTPRINTS\Altium_Footprint_Lib.PcbLib; Height: 1.00MM; Library Path: Y:\MIS_DATABASE\Library\ALTIUM_TOOL\SCHEMATICS_PARTS\MS_MISCPOWER_Library.schlib; Mfr_name: TEXAS INSTRUMENTS; Mistral Part No: 142018080020-R; Package: VSON-HR7; Part_type: ICS\POWER\CONVERTER; Project: TI_MAXIE_CPB; RoHS: RoHS; Temperature: -40°C+125°C; Tolerance: NA; Voltage: NA; Wattage: NA; Weight: 8.8mg; Datasheet: Y:\MIS_DATABASE\DATASHEETS\ICS\POWER\TPS62085.PDF
U72 = TLV71318PDQNR_X2SON4: IC 500mA LOW IQ LDO REGULATOR X2SON-4; Crtd /date: ALVY/160620; Custom_Duty: 15%; Customs_HS_Code: 85423100; Distributor_name: DIGIKEY; Distributor_part_number: 296-51790-1-ND; Footprint Path: Y:\MIS_DATABASE\Library\ALTIUM_TOOL\PCB_FOOTPRINTS\Altium_Footprint_Lib.PcbLib; Height: 0.40MM; Library Path: Y:\MIS_DATABASE\Library\ALTIUM_TOOL\SCHEMATICS_PARTS\MS_MISCPOWER_Library.schlib; Mfr_name: TEXAS INSTRUMENTS; Mistral Part No: 142020060013-R; Package: X2SON-4; Part_type: ICS\POWER\VOLTAGE REGULATOR; Project: AM64x-GP_EVM BRD; RoHS: RoHS; Temperature: -40°C+125°C; Tolerance: NA; Voltage: NA; Wattage: NA; Weight: 1.1mg; Datasheet: Y:\MIS_DATABASE\DATASHEETS\ICS\POWER\TLV755P.PDF
U103 = SN74LVC1G32DBVR_SOT23-5: IC SINGAL 2 INPUT POSITIVE OR GATE SOT23-5; Chkd/date: MANIRAJA/051017; Crtd /date: MAZHAR/070806; Custom_Duty: 15%; Customs_HS_Code: 85423100; Distributor_name: DIGIKEY; Distributor_part_number: 296-9847-1-ND; Height: 1.45MM; Mfr_name: TEXAS INSTRUMENTS; Mistral Part No: 141009030236-R; Package: SOT23-5; Part_type: ICS\DIGITAL\GATES; Project: SVDO_RMB_MMA; RoHS: RoHS; Temperature: -40°C+85°C; Tolerance: NA; Voltage: NA; Wattage: NA; Weight: 6.3mg; Datasheet: Y:\MIS_DATABASE\DATASHEETS\ICS\DIGITAL\GATES\SN74LVC1G32.PDF
U104 = SN74LVC1G08DBVRE4_SOT23-5: IC SINGLE 2-INPUT POSITIVE AND GATE SOT23-5; Chkd/date: SUHAS/221010; Crtd /date: USMAN/151008; Custom_Duty: 15%; Customs_HS_Code: 85423100; Distributor_name: DIGIKEY; Distributor_part_number: SN74LVC1G08DBVRE4-ND; Height: 1.45MM; Mfr_name: TEXAS INSTRUMENTS; Mistral Part No: 141009060026-R; Part_type: ICS\DIGITAL\GATES; Project: KHAN_MAIN; RoHS: Sb/ Br FREE; Temperature: -40°C+85°C; Datasheet: Y:\MIS_DATABASE\DATASHEETS\ICS\DIGITAL\GATES\SN74LVC1G08.PDF
C218 = CAP: CAP CERAMIC 0.22uF 6.3V 10% X6S AUTO 0201; Chkd/date: MANIRAJA/220219; Crtd /date: ALVY/220219; Custom_Duty: 15%; Customs_HS_Code: 85322990; Distributor_name: DIGIKEY; Distributor_part_number: 490-12230-1-ND; Footprint Path: Y:\MIS_DATABASE\Library\ALTIUM_TOOL\PCB_FOOTPRINTS\Altium_Footprint_Lib.PcbLib; Height: 0.33MM; Library Path: Y:\MIS_DATABASE\Library\ALTIUM_TOOL\SCHEMATICS_PARTS\MS_DISCRETE_Library.schlib; Mfr_name: MURATA; Mfr_part_number: GRT033C80J224KE01D; Mistral Part No: 120019020011-R; Package: 0201; Part_type: CAPACITORS\CERAMIC; Project: TI_J7ES_EVM_SOM; RoHS: RoHS; Temperature: -55°C+105°C; Tolerance: 10%; Voltage: 6.3V; Wattage: NA; Weight: 0.17mg; Datasheet: Y:\MIS_DATABASE\DATASHEETS\CAPACITORS\MURATA-GCM-SER.PDF
C452 = CAP: CAP CERAMIC 2.2uF 35V 10% X5R 0603; Chkd/date: VASANTHA/270117; Crtd /date: MANIRAJA/270117; Custom_Duty: 15%; Customs_HS_Code: 85322990; Distributor_name: DIGIKEY; Distributor_part_number: 490-7204-1-ND; Footprint Path: Y:\MIS_DATABASE\Library\ALTIUM_TOOL\PCB_FOOTPRINTS\Altium_Footprint_Lib.PcbLib; Height: 0.90MM; Library Path: Y:\MIS_DATABASE\Library\ALTIUM_TOOL\SCHEMATICS_PARTS\MS_DISCRETE_Library.schlib; Mfr_name: MURATA; Mfr_part_number: GRM188R6YA225KA12D; Mistral Part No: 120017010016-R; Package: 0603; Part_type: CAPACITORS\CERAMIC; Project: SD820_NANO_SOM; RoHS: RoHS; Temperature: -55°C+85°C; Tolerance: 10%; Voltage: 35V; Wattage: NA; Weight: 6.3mg; Datasheet: Y:\MIS_DATABASE\DATASHEETS\CAPACITORS\MURATA-GXX-SER_NOV17.PDF
C458 = CAP: CAP CERAMIC 22uF 10V 20% X5R 0805; Chkd/date: MANIRAJA/210820; Crtd /date: ALVY/190820; Custom_Duty: 15%; Customs_HS_Code: 85322990; Distributor_name: DIGIKEY; Distributor_part_number: 732-7621-1-ND; Footprint Path: Y:\MIS_DATABASE\Library\ALTIUM_TOOL\PCB_FOOTPRINTS\Altium_Footprint_Lib.PcbLib; Height: 1.45MM; Library Path: Y:\MIS_DATABASE\Library\ALTIUM_TOOL\SCHEMATICS_PARTS\MS_DISCRETE_Library.schlib; Mfr_name: WURTH ELECTRONICS; Mfr_part_number: 885012107011; Mistral Part No: 120020080010-R; Package: 0805; Part_type: CAPACITORS\CERAMIC; Project: AM64x_EVM_BRD; RoHS: RoHS; Temperature: -55°C+85°C; Tolerance: 20%; Voltage: 10V; Wattage: NA; Weight: 5.5mg; Datasheet: Y:\MIS_DATABASE\DATASHEETS\CAPACITORS\885012107011.PDF
L9 = INDUCTOR: IND POWER 10uH 1.2A 20% SMD; Chkd/date: MANIRAJA/180917; Crtd /date: MANIRAJA/180917; Custom_Duty: 24%; Customs_HS_Code: 85369090; Distributor_name: DIGIKEY; Distributor_part_number: 732-5700-1-ND; Height: 2.00MM; Mfr_name: WURTH ELECTRONICS INC; Mfr_part_number: 74438336100; Mistral Part No: 130017090020-R; Package: SMD; Project: P4_RADAR_DI; RoHS: RoHS; Temperature: -40°C+125°C; Tolerance: 20%; Voltage: NA; Wattage: NA; Weight: NA; Datasheet: Y:\MIS_DATABASE\DATASHEETS\DISCRETES\INDUCTORS\74438336100.PDF
LD24 LD25 = DIODE_LED: DIODE LED BRIGHT GREEN SMD; Chkd/date: MANIRAJA/180820; Crtd /date: ALVY/180820; Custom_Duty: 24%; Customs_HS_Code: 85439000; Distributor_name: DIGIKEY; Distributor_part_number: 732-4986-1-ND; Footprint Path: Y:\MIS_DATABASE\Library\ALTIUM_TOOL\PCB_FOOTPRINTS\Altium_Footprint_Lib.PcbLib; Height: 0.80MM; Library Path: Y:\MIS_DATABASE\Library\ALTIUM_TOOL\SCHEMATICS_PARTS\MS_OPTO_Library.schlib; Mfr_name: WURTH ELECTRONICS; Mistral Part No: 130020080012-R; Package: SMD; Part_type: OPTO\LED; Project: AM64x_EVM_BRD; RoHS: RoHS; Temperature: -40°C+85°C; Tolerance: NA; Voltage: NA; Wattage: NA; Weight: 10mg; Datasheet: Y:\MIS_DATABASE\DATASHEETS\DISCRETES\LEDS\150080VS75000.PDF
R201 = RESISTOR: RES 220E 1/10W 5% 0402; Chkd/date: VASANTHA/291216; Crtd /date: GEETHA/260406; Custom_Duty: 15%; Customs_HS_Code: 85332119; Distributor_name: DIGIKEY; Distributor_part_number: P220JCT-ND; Footprint Path: Y:\MIS_DATABASE\Library\ALTIUM_TOOL\PCB_FOOTPRINTS\Altium_Footprint_Lib.PcbLib; Height: 0.40MM; Library Path: Y:\MIS_DATABASE\Library\ALTIUM_TOOL\SCHEMATICS_PARTS\MS_DISCRETE_Library.schlib; Mfr_name: PANASONIC-ECG; Mfr_part_number: ERJ-2GEJ221X; Mistral Part No: 110009030506-R; Package: 0402; Part_type: RESISTORS\FIXED; Project: RED EYE; RoHS: RoHS; Temperature: -55°C+155°C; Tolerance: 5%; Voltage: NA; Wattage: 1/10W; Weight: 0.8mg; Datasheet: Y:\MIS_DATABASE\DATASHEETS\RESISTORS\PAN-ERJSER_NOV17.PDF
R231 = RESISTOR: RES 4.7K 1/16W 5% 0402; Chkd/date: VASANTHA/130516; Crtd /date: VASANTHA/130516; Custom_Duty: 15%; Customs_HS_Code: 85332119; Distributor_name: DIGIKEY; Distributor_part_number: 311-4.7KJRCT-ND; Footprint Path: Y:\MIS_DATABASE\Library\ALTIUM_TOOL\PCB_FOOTPRINTS\Altium_Footprint_Lib.PcbLib; Height: 0.40MM; Library Path: Y:\MIS_DATABASE\Library\ALTIUM_TOOL\SCHEMATICS_PARTS\MS_DISCRETE_Library.schlib; Mfr_name: YAGEO AMERICA; Mfr_part_number: RC0402JR-074K7L; Mistral Part No: 110011060001-R; Package: 0402; Part_type: RESISTORS\FIXED; Project: TMDXCSK368; RoHS: RoHS; Temperature: -55°C+155°C; Tolerance: 5%; Voltage: NA; Wattage: 1/16W; Weight: 0.65mg; Datasheet: Y:\MIS_DATABASE\DATASHEETS\RESISTORS\RCXXXXL-SER_MAR18.PDF
R232 = RESISTOR: RES 10K 1/16W 1% 0402; Chkd/date: VASANTHA/201216; Crtd /date: GEETHA/290506; Custom_Duty: 15%; Customs_HS_Code: 85332119; Distributor_name: DIGIKEY; Distributor_part_number: 311-10.0KLRTR-ND; Footprint Path: Y:\MIS_DATABASE\Library\ALTIUM_TOOL\PCB_FOOTPRINTS\Altium_Footprint_Lib.PcbLib; Height: 0.40MM; Library Path: Y:\MIS_DATABASE\Library\ALTIUM_TOOL\SCHEMATICS_PARTS\MS_DISCRETE_Library.schlib; Mfr_name: YAGEO AMERICA; Mfr_part_number: RC0402FR-0710KL; Mistral Part No: 110015090015-R; Package: 0402; Part_type: RESISTORS\FIXED; Project: VOCERA; RoHS: RoHS; Temperature: -55°C+155°C; Tolerance: 1%; Voltage: NA; Wattage: 1/16W; Weight: 0.65mg; Datasheet: Y:\MIS_DATABASE\DATASHEETS\RESISTORS\RCXXXXL-SER_MAR18.PDF
R361 = RESISTOR: RES 7.5K 1/16W 1% 0402; Chkd/date: MANIRAJA/060619; Crtd /date: ALVY/040619; Custom_Duty: 15%; Customs_HS_Code: 85332119; Distributor_name: DIGIKEY; Distributor_part_number: 541-7.50KLCT-ND; Footprint Path: Y:\MIS_DATABASE\Library\ALTIUM_TOOL\PCB_FOOTPRINTS\Altium_Footprint_Lib.PcbLib; Height: 0.40MM; Library Path: Y:\MIS_DATABASE\Library\ALTIUM_TOOL\SCHEMATICS_PARTS\MS_DISCRETE_Library.schlib; Mfr_name: VISHAY; Mfr_part_number: CRCW04027K50FKED; Mistral Part No: 110019060009-R; Package: 0402; Part_type: RESISTORS\FIXED; Project: MYTHIC_FORMFACTOR_BRD; RoHS: RoHS; Temperature: -55°C+155°C; Tolerance: 1%; Voltage: NA; Wattage: 1/16W; Weight: 0.65mg; Datasheet: Y:\MIS_DATABASE\DATASHEETS\RESISTORS\CRCW0603.PDF
R556 = RESISTOR: RES 160E 1/10W 1% 0402; Chkd/date: VASANTHA/170217; Crtd /date: CHAITHANYA/220512; Custom_Duty: 15%; Customs_HS_Code: 85332119; Distributor_name: DIGIKEY; Distributor_part_number: P160LCT-ND; Footprint Path: Y:\MIS_DATABASE\Library\ALTIUM_TOOL\PCB_FOOTPRINTS\Altium_Footprint_Lib.PcbLib; Height: 0.40MM; Library Path: Y:\MIS_DATABASE\Library\ALTIUM_TOOL\SCHEMATICS_PARTS\MS_DISCRETE_Library.schlib; Mfr_name: PANASONIC-ECG; Mfr_part_number: ERJ-2RKF1600X; Mistral Part No: 110012050018-R; Package: 0402; Part_type: RESISTORS\FIXED; Project: GEN_3-8; RoHS: RoHS; Temperature: -55°C+155°C; Tolerance: 1%; Voltage: NA; Wattage: 1/10W; Weight: 0.8mg; Datasheet: Y:\MIS_DATABASE\DATASHEETS\RESISTORS\PAN-ERJSER_NOV17.PDF
U62 = TPS73501DRVR_SON6: IC 500mA LOW DROPOUT HIGH PSRR LINEAR REGULATOR SON6; Chkd/date: MANIRAJA/161117; Crtd /date: MANIRAJA/161117; Custom_Duty: 15%; Customs_HS_Code: 85423100; Distributor_name: DIGIKEY; Distributor_part_number: 296-27480-1-ND; Height: 0.80MM; Mfr_name: TEXAS INSTRUMENTS; Mistral Part No: 142017110007-R; Package: SON6; Part_type: ICS\POWER\VOLTAGE REGULATOR; Project: TI_MAXIE_CPB; RoHS: RoHS; Temperature: -40°C+125°C; Tolerance: NA; Voltage: NA; Wattage: NA; Weight: 9.7mg; Datasheet: Y:\MIS_DATABASE\DATASHEETS\ICS\POWER\TPS735.PDF
U68 = TPS51206DSQR_WSON10: IC SINK/SOURCE DDR TERMINATION REGULATOR WSON10; Chkd/date: MANIRAJA/220917; Crtd /date: MANIRAJA/220917; Custom_Duty: 15%; Customs_HS_Code: 85423100; Distributor_name: DIGIKEY; Distributor_part_number: 296-28767-1-ND; Footprint Path: Y:\MIS_DATABASE\Library\ALTIUM_TOOL\PCB_FOOTPRINTS\Altium_Footprint_Lib.PcbLib; Height: 0.80MM; Library Path: Y:\MIS_DATABASE\Library\ALTIUM_TOOL\SCHEMATICS_PARTS\MS_MISCPOWER_Library.schlib; Mfr_name: TEXAS INSTRUMENTS; Mistral Part No: 142017090016-R; Package: WSON10; Part_type: ICS\POWER\VOLTAGE REGULATOR; Project: TI_MAXIE_CPB; RoHS: RoHS; Temperature: -40°C+85°C; Tolerance: NA; Voltage: NA; Wattage: NA; Weight: NA; Datasheet: Y:\MIS_DATABASE\DATASHEETS\ICS\POWER\TPS51206.PDF
U77 = TLV71318PDQNR_X2SON4: IC 200mA LOW IQ LOW NOISE LDO REGULATOR FOR PORTABLE DEVICE X2SON-4; Chkd/date: MANIRAJA/270520; Crtd /date: ALVY/250520; Custom_Duty: 15%; Customs_HS_Code: 85423100; Distributor_name: DIGIKEY; Distributor_part_number: 296-40623-1-ND; Footprint Path: Y:\MIS_DATABASE\Library\ALTIUM_TOOL\PCB_FOOTPRINTS\Altium_Footprint_Lib.PcbLib; Height: 0.40MM; Library Path: Y:\MIS_DATABASE\Library\ALTIUM_TOOL\SCHEMATICS_PARTS\MS_MISCPOWER_Library.schlib; Mfr_name: TEXAS INSTRUMENTS; Mistral Part No: 142020050029-R; Package: X2SON-4; Part_type: ICS\POWER\VOLTAGE REGULATOR; Project: AM64x-GP_EVM BRD; RoHS: RoHS; Temperature: -40°C+125°C; Tolerance: NA; Voltage: NA; Wattage: NA; Weight: 4.1mg; Datasheet: Y:\MIS_DATABASE\DATASHEETS\ICS\POWER\TLV707X.PDF
U97 = TPS62177_WSON10: IC 3.3V 0.5A STEP DOWN CONVERTER WITH SLEEP MODE WSON10; Chkd/date: MANIRAJA/170719; Crtd /date: MANIRAJA/170719; Custom_Duty: 15%; Customs_HS_Code: 85423100; Distributor_name: DIGIKEY; Distributor_part_number: 296-41856-1-ND; Footprint Path: Y:\MIS_DATABASE\Library\ALTIUM_TOOL\PCB_FOOTPRINTS\Altium_Footprint_Lib.PcbLib; Height: 0.80MM; Library Path: Y:\MIS_DATABASE\Library\ALTIUM_TOOL\SCHEMATICS_PARTS\MS_MISCPOWER_Library.schlib; Mfr_name: TEXAS INSTRUMENTS; Mistral Part No: 142019070007-R; Package: WSON10; Part_type: ICS\POWER\DC-DC CONVERTER; Project: TI_MAXIE_CPB; RoHS: RoHS; Temperature: -40°C+85°C; Tolerance: NA; Voltage: NA; Wattage: NA; Weight: 15mg; Datasheet: Y:\MIS_DATABASE\DATASHEETS\ICS\POWER\TPS62177.PDF
U100 = TLV71318PDQNR_X2SON4: IC 200mA LOW IQ LOW NOISE LDO REGULATOR FOR PORTABLE DEVICE X2SON-4; Chkd/date: MANIRAJA/170420; Crtd /date: ALVY/160420; Custom_Duty: 15%; Customs_HS_Code: 85423100; Distributor_name: DIGIKEY; Distributor_part_number: 296-39289-1-ND; Footprint Path: Y:\MIS_DATABASE\Library\ALTIUM_TOOL\PCB_FOOTPRINTS\Altium_Footprint_Lib.PcbLib; Height: 0.40MM; Library Path: Y:\MIS_DATABASE\Library\ALTIUM_TOOL\SCHEMATICS_PARTS\MS_MISCPOWER_Library.schlib; Mfr_name: TEXAS INSTRUMENTS; Mistral Part No: 142020040017-R; Package: X2SON-4; Part_type: ICS\POWER\VOLTAGE REGULATOR; Project: AM64x-GP_EVM BRD; RoHS: RoHS; Temperature: -40°C+125°C; Tolerance: NA; Voltage: NA; Wattage: NA; Weight: 1.5mg; Datasheet: Y:\MIS_DATABASE\DATASHEETS\ICS\POWER\TLV707X.PDF

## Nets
DGND: C9.2 C20.2 C25.2 C28.2 C33.2 C37.2 C77.2 C95.2 C122.2 C126.2 C127.2 C129.2 C199.1 C200.2 C201.2 C202.2 C208.2 C210.1 C211.2 C213.1 C215.2 C217.2 C218.2 C219.2 C243.2 C265.2 C280.2 C286.2 C402.2 C403.2 C452.2 C458.2 C459.2 C471.2 C479.2 C486.2 C495.1 LD24.1(CATHODE) LD25.1(CATHODE) R29.2 R49.2 R117.1 R145.2 R213.2 R231.2 R263.1 R364.2 U5.1(PGND) U5.11(AGND) U9.1(PGND) U9.11(AGND) U12.5(GND) U12.6(GND) U12.9(EP) U25.3(AGND) U25.5(PGND) U32.1(PGND) U32.11(AGND) U33.3(GND) U33.7(EP) U62.3(GND) U62.7(EP) U65.5(GND) U68.4(PGND) U68.8(GND) U68.11(EP) U72.2(GND) U72.5(EP) U77.2(GND) U77.5(EP) U97.1(PGND) U97.5(FB) U97.6(AGND) U97.11(EP) U100.2(GND) U100.5(EP) U103.3(GND) U104.3(GND) ; also on sheet 2 3 4 5 6 7 8 9 10 11 12 13 14 17 18 19 20 21 22 23 24 25 26 27 28 29 30 39 40
VCC1V1_PG: R396.1 U32.5(PG) ; also on sheet 8
VCC1V2_DDR: C20.1 L2.2 R214.1 TP4.1(TP) U5.3(VOS) ; also on sheet 14
VCC1V2_PG: R219.1 U5.5(PG) U103.1(A) U104.1(A) ; also on sheet 8
VCC1V8: C217.1 L8.2 TP51.1(TP) U65.3(FB) U65.4(VOS) ; also on sheet 11 12 13 14 18 21 24
VCC2V5_PG: R225.1 U9.5(PG) ; also on sheet 8
VCC3V3_PREREG: C9.1 C37.1 C95.1 C126.1 C211.1 C265.1 C479.1 C495.2 R58.2 R123.2 R219.2 U5.7(PVIN) U5.8(AVIN) U12.3(VIN1) U12.4(VIN2) U25.7(VIN) U33.6(IN) U65.7(VIN) U72.4(IN) U103.5(VCC) U104.5(VCC) ; also on sheet 17 25
VCC3V3_SYS_PG: R580.2 R583.2 R589.2 TP49.1(TP) TP97.1(TP) ; also on sheet 17
VCC3V3_TA: C458.1 L9.2 R201.1 R535.2 TP96.1(TP) U97.8(SLEEP) U97.10(VOS) ; also on sheet 17 29 30
VCC_3V3_SYS: C25.1 C127.1 C199.2 C208.1 C219.1 C286.1 C459.1 R143.2 R225.2 R396.2 U9.7(PVIN) U9.8(AVIN) U32.7(PVIN) U32.8(AVIN) U62.6(IN) U68.2(VLDOIN) U68.10(VDD) U77.4(IN) U100.4(IN) ; also on sheet 2 5 6 7 8 10 11 12 13 14 17 18 19 20 21 23 24 25 26 27 29 30 39 40
VCC_CORE: C77.1 C486.1 L4.2 TP23.1(TP) ; also on sheet 14
VCC_CORE_EN: R584.2 TP24.1(TP) U103.4(Y)
VCC_CORE_FB: C96.2 R117.2 R118.2 U25.2(FB)
VCC_CORE_PG: R123.1 U25.8(PG) U104.2(B) ; also on sheet 8 17
VDD1V8_PG: C403.1 R143.1 R581.2 TP50.1(TP) U33.5(PG) U65.2(PG) ; also on sheet 8
VDD_0V85: C33.1 TP8.1(TP) U12.8(VOUT) ; also on sheet 14
VDD_0V85_EN: R57.1 U104.4(Y)
VDD_0V85_PG: R58.1 U12.2(PG) U103.2(B) ; also on sheet 8
VDD_1V0: C280.1 TP56.1(TP) U77.1(OUT) ; also on sheet 2
VDD_1V1: C122.1 L7.2 R361.1 TP28.1(TP) U32.3(VOS) ; also on sheet 39 40
VDD_2V5: C28.1 L1.2 R232.1 TP6.1(TP) U9.3(VOS) ; also on sheet 2 39 40
VDD_2V8: C471.1 R556.1 TP99.1(TP) U100.1(OUT) ; also on sheet 6
VDD_CORE: C96.1 R118.1 TP14.1(TP) ; also on sheet 3 4 14 25
VDD_DDR4: C213.2 U68.1(VDDQSNS) ; also on sheet 3 4 14 22
VDDA1V8: C129.1 R144.1 TP29.1(TP) U33.1(OUT) ; also on sheet 14
VDDAR_CORE: R44.1 TP10.1(TP) ; also on sheet 4 14
VDDR_VTT: C210.2 TP48.1(TP) U68.3(VTT) U68.5(VTTSNS) ; also on sheet 22
VIN_MON_PORz_3V3_PG: R585.2 R586.2 R587.2 R588.2 TP45.1(TP) ; also on sheet 17 25
DDR_VREFCA: C218.1 U68.6(VTTREF) ; also on sheet 22
DDR_VTT_EN_3V3: R29.1 TP7.1(TP) U68.7(S3) U68.9(S5) ; also on sheet 13
VMAIN: C452.1 R500.1 U97.2(VIN) ; also on sheet 4 5 8 17
VPP_1V8: C243.1 TP52.1(TP) U72.1(OUT) ; also on sheet 4
VPP_DDR_2V5: C201.1 TP47.1(TP) U62.1(OUT) ; also on sheet 22
VPP_LDO_EN: R263.2 R582.2 TP53.1(TP) ; also on sheet 13
N17786037: L1.1 U9.2(SW)
N17786049: R231.1 R232.2 U9.4(FB)
N19031494: C215.1 U9.9(SS/TR)
N20142928: C200.1 U62.2(NR/FB)
N26016842: L9.1 U97.9(SW)
N26016868: R535.1 TP98.1(TP) U97.7(PG)
N26016893: R500.2 U97.3(EN)
N26733190: R361.2 R364.1 U32.4(FB)
N26733205: L7.1 U32.2(SW)
N26733231: C402.1 U32.9(SS/TR)
N26735382: C202.1 U5.9(SS/TR)
N26735416: R213.1 R214.2 U5.4(FB)
N26735457: L2.1 U5.2(SW)
N26735496: L8.1 U65.6(SW)
N26735653: R144.2 R145.1 U33.2(FB)
N26736579: L4.1 U25.6(SW)
N26736751: R57.2 U12.1(EN)
N26736805: R44.2 R49.1 U12.7(FB)
N27943339: R580.1 U65.1(EN)
N27943633: R581.1 U5.6(EN)
N27943804: R582.1 U72.3(EN)
N27943890: R583.1 U33.4(EN)
N27943939: R584.1 U25.1(EN)
N27944274: R585.1 U9.6(EN)
N27944496: R586.1 U62.4(EN)
N27944776: R587.1 U32.6(EN)
N27944822: R588.1 U77.3(EN)
N27945052: R589.1 U100.3(EN)
N28118607: LD25.2(ANODE) R556.2
N28118686: LD24.2(ANODE) R201.2

Not connected (* = marked no-connect by the designer): U5 10(MODE)*; U9 10(MODE)*; U25 4(NC)*; U32 10(MODE)*; U62 5(NC)*; U97 4(NC)*

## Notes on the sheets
sheet 15
- SoC POWER SUPPLY
- 1.8V IO, 3.0AMPS SUPPLY
- 0.75 / 0.8 /0.85V, 3.0AMPS SUPPLY
- Rfb
- CORE VOLTAGE
- Rfb RES TO BE PLACED
- 0.75V
- Rfb = 24.9K
- 1.2V, 2.0AMPS SUPPLY
- 0.80V
- Rfb = 33.2K
- 0.85V
- Rfb = 41.2K
- 0.85 V, 1.5AMPS SUPPLY
- Ren
- 1.8V VPP, 0.15AMPS SUPPLY
- If VDD_CORE = 0.75V,
  Mount Ren
  If VDD_CORE =0.85
  DNI Ren
- 1.8V Analog , 1AMPS SUPPLY
- Off Page Connections
sheet 16
- PERIPHERAL POWER SUPPLY
- TEST AUTOMATION BOARD POWER
- VTT SUPPLY FOR DDR4
- 1.1V ETHERNET PHY POWER SUPPLY
- 2.5V, 2.0AMPS SUPPLY
- 1.0V ETHERNET PHY POWER SUPPLY
- 2.5V, .5 AMPS SUPPLY
- 2.8V , 0.15AMPS SUPPLY
- Off Page Connections
